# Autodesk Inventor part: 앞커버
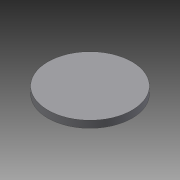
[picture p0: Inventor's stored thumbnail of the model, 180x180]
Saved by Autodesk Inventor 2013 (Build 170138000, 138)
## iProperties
Created: 2024-02
Part Number: 앞커버
Material: 알루미늄 6061
Document SubType Name: Modeling
Designer: mdu-01
Density: 2.71 g/cm^3
Mass: 306.094 g
Surface Area: 299.031 cm^2
Volume: 112.95 cm^3
Author: mdu-01
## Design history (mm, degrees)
sketch "스케치1"
  geometry: C1 r 60 at (0, 0) reference; C2 r 46 at (0, 0) reference; C3 r 15 at (0, 0) reference; C4 r 11 at (0, -31) reference; A1 r 41 centre (0, 0) between (20.39, -35.57) and (-20.39, -35.57); A2 r 20 centre (0, 0) between (12.218, -15.835) and (-12.218, -15.835); A3 r 16 centre (0, -31) between (-11.832, -20.229) and (-15.914, -32.657); A4 r 16 centre (0, -31) between (15.914, -32.657) and (11.832, -20.229); A5 r 3 centre (-14.05, -18.21) between (-11.832, -20.229) and (-12.218, -15.835); A6 r 3 centre (14.05, -18.21) between (12.218, -15.835) and (11.832, -20.229); A7 r 3 centre (18.898, -32.968) between (15.914, -32.657) and (20.39, -35.57); A8 r 3 centre (-18.898, -32.968) between (-20.39, -35.57) and (-15.914, -32.657); 1 further point
  constraints: 16 point on circle, 8 centre point, 8 tangent, 4 equal radius
  dimensions: "d0" = 5 radial gap between concentric circles of C2 A1; "d1" = 5 radial gap between concentric circles of A2 C3; "d3" = 5 radial gap between concentric circles of A4 C4; "d4" = 3 radius of A5
  node "참조1"
  node "참조2"
  node "참조3"
  node "참조4"
extrude "돌출1" new body sketch "스케치1" distance "d5" = 10; taper "d6" = 0 deg
extrude "돌출2" join sketch "스케치1" distance "d7" = 3; taper "d8" = 0 deg
sketch "스케치2"
  geometry: C1 r 20 at (0, 0); 1 further point
  constraints: 1 centre point, 1 coincident
  dimensions: "d9" = 40 diameter of C1
extrude "돌출3" join sketch "스케치2" distance "d10" = 7; taper "d11" = 0 deg
fillet "모깎기1" dims "d12" = 3
chamfer "모따기1" distance "d13" = 1; stored, may be unused: second distance "d14" = 2, angle "d15" = 45 deg
sketch "스케치3"
  geometry: C1 r 1.621 at (0, 52) reference; 1 further point
hole "구멍1" sketch "스케치3" at (0, 52) diameter "d16" = 4.5; stored, may be unused: countersink angle "d20" = 90 deg, drill point angle "d22" = 118 deg; dims "d17" = 6, "d18" = 8, "d19" = 4.4, "d21" = 8
sketch "스케치4"
  geometry: L1 (15, 3.7)-(15, -2.7) reference; L2 (-14.7, 4)-(14.7, 4) reference; L3 (14.7, -3)-(-14.7, -3) reference; L4 (14.7, 4)-(13, 4); L5 (-17, 17)-(17, 17) reference; L6 (15, 16.2)-(15, 9); L7 (14.7, 8.7)-(13, 8.7); L8 (13, 8.7)-(13, 4); L9 (0, 17)-(0, -3); L10 (15.462, 17)-(15, 16.2); L11 (14.7, -3)-(15, -3); L12 (15, -3)-(15, -2.7); A1 r 0.3 centre (14.7, 3.7) between (15, 3.7) and (14.7, 4); A2 r 0.3 centre (14.7, 9) between (14.7, 8.7) and (15, 9); 1 further point
  constraints: 18 end point, 4 point on circle, 3 perpendicular, 3 tangent, 2 centre point, 2 midpoint, 2 point on line, 1 collinear, 1 parallel, 1 vertical, 2 other
  dimensions: "d26" = 2 distance from line of L4.end L1; "d28" = 0.3 radius of A2; "d29" = 30 diameter of L6 L9; "d30" = 8.3 distance between parallel lines of L7 L5; "d31" = 0.8 distance from line of L6.start L5; "d32" = 30 deg angle of L6 L10
revolve "회전1" sketch "스케치4" stored, may be unused: angle "d33" = 90 deg
sketch "스케치5"
  geometry: L1 (-20, 3.7)-(-20, -2.7) reference; L2 (-20.3, -3)-(-41.7, -3) reference; L3 (-41.7, 4)-(-20.3, 4) reference; L4 (-20.3, 4)-(-22, 4); L5 (-20, -2.7)-(-20, -3); L6 (-20, -3)-(-20.3, -3); L7 (-31, -3)-(-31, 7); L8 (-31, 7)-(-25, 7); A1 r 0.3 centre (-20.3, 3.7) between (-20, 3.7) and (-20.3, 4); A2 r 3 centre (-25, 4) between (-22, 4) and (-25, 7); 1 further point
  constraints: 12 end point, 4 perpendicular, 4 point on circle, 2 centre point, 2 point on line, 2 tangent, 1 midpoint, 1 vertical, 2 other
  dimensions: "d34" = 3 distance between parallel lines of L8 L3; "d35" = 2 distance from line of L4.end L1
revolve "회전2" sketch "스케치5" stored, may be unused: angle "d36" = 90 deg
chamfer "모따기2" distance "d37" = 1; stored, may be unused: second distance "d38" = 2, angle "d39" = 45 deg
node "솔리드1"
pattern_circular "원형 패턴1" dims angle "d24" = 360 deg
node "참조5"
node "참조6"
node "참조7"
node "참조8"
node "참조9"
other parameters: "d2" = 5
